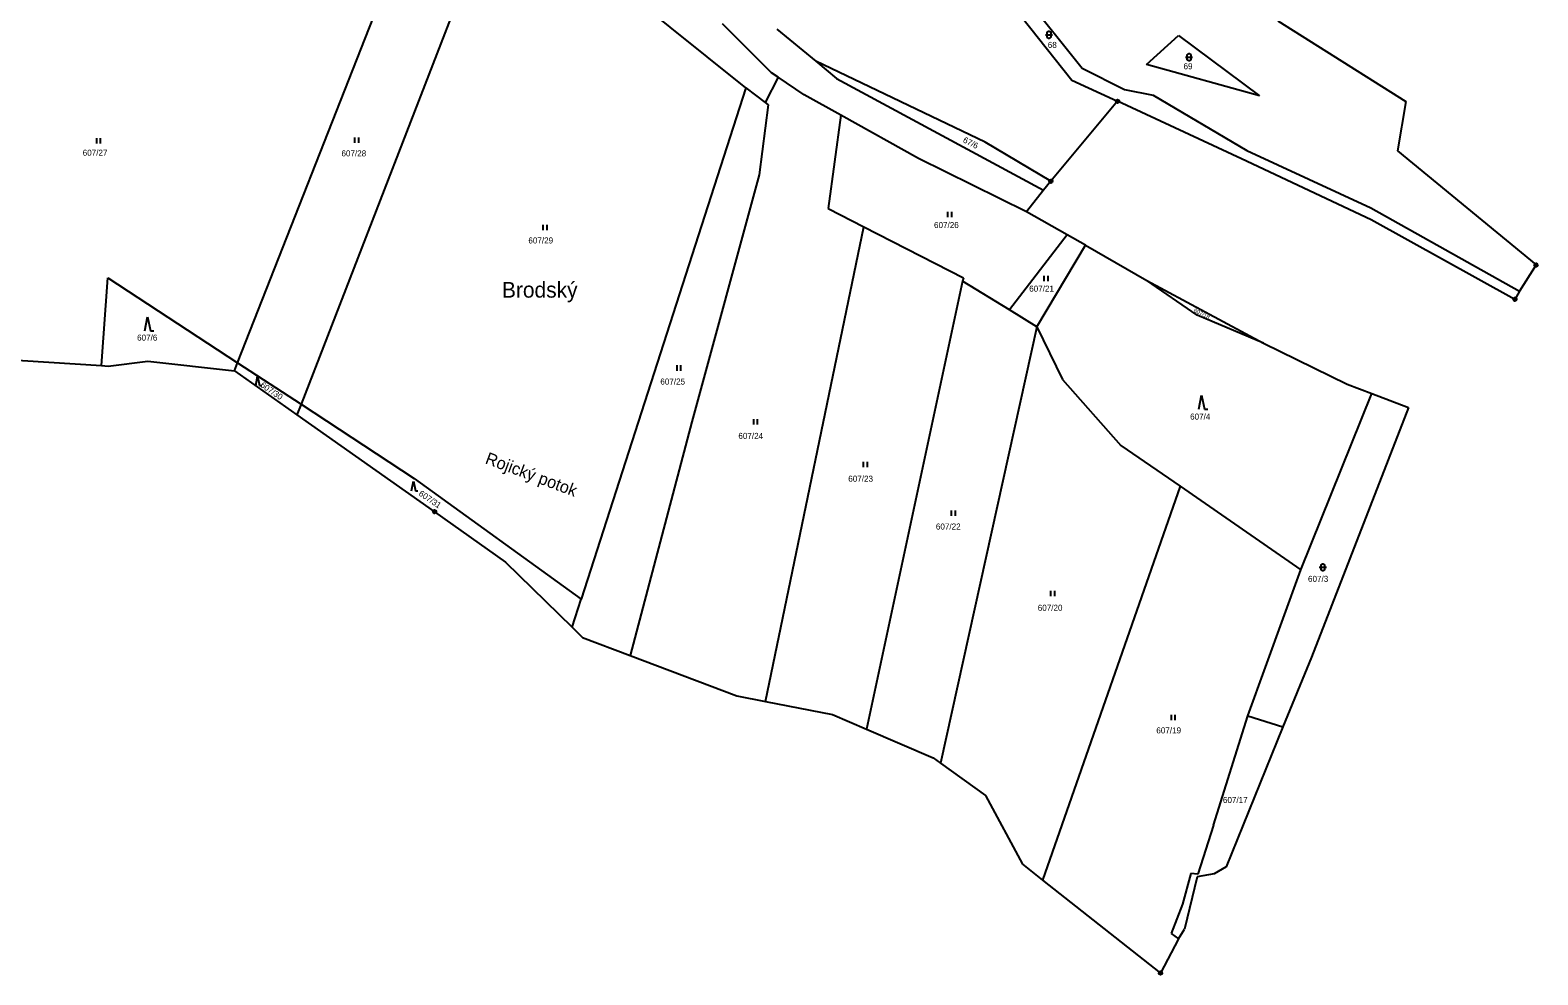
# Model space of a CAD drawing. Extents: x -794421 to -792735, y -1117671 to -1115559.
# Drawn here: x -793344.4 to -792920.6, y -1117671.2 to -1117405.7 of the extents above; entities that cross this region are included whole.
import ezdxf

# ---------------------------------------------------------------- set-up
doc = ezdxf.new("R2010")
doc.units = 0
for name, color, linetype in [('Vrstva 1', 7, 'Continuous'), ('Vrstva 14', 7, 'Continuous'), ('Vrstva 23', 7, 'Continuous'), ('Vrstva 28', 7, 'Continuous'), ('Vrstva 39', 7, 'Continuous'), ('Vrstva 4', 7, 'Continuous'), ('Vrstva 43', 7, 'Continuous')]:
    doc.layers.add(name, color=color, linetype=linetype)

msp = doc.modelspace()

# ---------------------------------------------------------------- linework, layer by layer
at = {"layer": 'Vrstva 1'}
for p, q in [((-793286.1, -1117499.19), (-793232.53, -1117362.94)), ((-793214.85, -1117373.01), (-793268.27, -1117510.87)), ((-793143.2, -1117421.9), (-793178.43, -1117393.62)), ((-793072.2, -1117393.73), (-793051.64, -1117419.77)), ((-793068.56, -1117391.53), (-793048.75, -1117416.41)), ((-793136.06, -1117417.71), (-793149.83, -1117403.92)), ((-793134.52, -1117405.39), (-793123.59, -1117414.41)), ((-793030.58, -1117415.37), (-793021.66, -1117407.23)), ((-793021.66, -1117407.23), (-792998.85, -1117424.15)), ((-793123.59, -1117414.41), (-793117.73, -1117419.25)), ((-793075.95, -1117437.2), (-793123.59, -1117414.41)), ((-792998.85, -1117424.15), (-793030.58, -1117415.37)), ((-793134.19, -1117418.96), (-793137.78, -1117426.04)), ((-793134.19, -1117418.96), (-793136.06, -1117417.71)), ((-793126.8, -1117423.9), (-793134.19, -1117418.96)), ((-793117.73, -1117419.25), (-793059.57, -1117450.65)), ((-793051.64, -1117419.77), (-793038.78, -1117425.69)), ((-793048.75, -1117416.41), (-793036.78, -1117422.39)), ((-793143.2, -1117421.9), (-793189.53, -1117565.63)), ((-793143.2, -1117421.9), (-793137.78, -1117426.04)), ((-793116.56, -1117429.62), (-793126.8, -1117423.9)), ((-793036.78, -1117422.39), (-793028.75, -1117423.98)), ((-793028.75, -1117423.98), (-793002.45, -1117439.49)), ((-793136.98, -1117426.66), (-793139.46, -1117446.37)), ((-793137.78, -1117426.04), (-793136.98, -1117426.66)), ((-793116.56, -1117429.62), (-793120.12, -1117455.82)), ((-793094.72, -1117441.81), (-793116.56, -1117429.62)), ((-793057.52, -1117448.19), (-793075.95, -1117437.2)), ((-793064.39, -1117456.77), (-793094.72, -1117441.81)), ((-793002.45, -1117439.49), (-792967.59, -1117455.63)), ((-793139.46, -1117446.37), (-793158.4, -1117515.77)), ((-793120.12, -1117455.82), (-793110.11, -1117460.97)), ((-792967.59, -1117455.63), (-792925.73, -1117479.04)), ((-793137.7, -1117594.41), (-793110.11, -1117460.97)), ((-793110.11, -1117460.97), (-793082.1, -1117475.33)), ((-793052.96, -1117463.24), (-793069.16, -1117484.35)), ((-793061.46, -1117489.1), (-793047.78, -1117466.17)), ((-793324.32, -1117499.98), (-793322.58, -1117475.28)), ((-793322.58, -1117475.28), (-793286.1, -1117499.19)), ((-793082.1, -1117475.33), (-793082.3, -1117476.24)), ((-793082.3, -1117476.24), (-793109.33, -1117602.18)), ((-793069.16, -1117484.35), (-793082.3, -1117476.24)), ((-793016.37, -1117485.78), (-793030.56, -1117476.1)), ((-793061.46, -1117489.1), (-793069.16, -1117484.35)), ((-792997.7, -1117493.71), (-793016.37, -1117485.78)), ((-793061.46, -1117489.1), (-793088.55, -1117611.72)), ((-793061.46, -1117489.1), (-793054.2, -1117503.86)), ((-793287, -1117501.49), (-793286.1, -1117499.19)), ((-793286.1, -1117499.19), (-793268.27, -1117510.87)), ((-793054.2, -1117503.86), (-793037.83, -1117522.49)), ((-792987.22, -1117557.42), (-792967.25, -1117507.86)), ((-793268.27, -1117510.87), (-793269.42, -1117513.84)), ((-793268.27, -1117510.87), (-793236.49, -1117531.69)), ((-793158.4, -1117515.77), (-793175.72, -1117581.5)), ((-793037.83, -1117522.49), (-793021.17, -1117533.91)), ((-793236.49, -1117531.69), (-793189.53, -1117565.63)), ((-793021.17, -1117533.91), (-793059.81, -1117644.62)), ((-793021.17, -1117533.91), (-792987.22, -1117557.42)), ((-793002.15, -1117598.46), (-792987.22, -1117557.42)), ((-793192.08, -1117573.55), (-793189.53, -1117565.63)), ((-793011.83, -1117629.19), (-793002.15, -1117598.46)), ((-793002.15, -1117598.46), (-792992.26, -1117601.54)), ((-793011.83, -1117629.19), (-793016.15, -1117642.96)), ((-793018.19, -1117642.77), (-793020.47, -1117651.32)), ((-793016.15, -1117642.96), (-793018.19, -1117642.77)), ((-793020.47, -1117651.32), (-793023.73, -1117659.61)), ((-793023.73, -1117659.61), (-793021.58, -1117661.13))]:
    msp.add_line(p, q, dxfattribs=at)
at = {"layer": 'Vrstva 23'}
for p, q in [((-793059.05, -1117407.01), (-793057.05, -1117407.01)), ((-793058.55, -1117406.41), (-793058.45, -1117406.21)), ((-793058.55, -1117407.61), (-793058.55, -1117406.41)), ((-793058.45, -1117407.81), (-793058.55, -1117407.61)), ((-793058.45, -1117406.21), (-793058.35, -1117406.11)), ((-793058.35, -1117407.91), (-793058.45, -1117407.81)), ((-793058.35, -1117406.11), (-793058.15, -1117406.01)), ((-793058.15, -1117408.01), (-793058.35, -1117407.91)), ((-793058.15, -1117406.01), (-793057.95, -1117406.01)), ((-793057.95, -1117406.01), (-793057.75, -1117406.11)), ((-793057.75, -1117407.91), (-793057.95, -1117408.01)), ((-793057.75, -1117406.11), (-793057.65, -1117406.21)), ((-793057.65, -1117407.81), (-793057.75, -1117407.91)), ((-793057.65, -1117406.21), (-793057.55, -1117406.41)), ((-793057.55, -1117407.61), (-793057.65, -1117407.81)), ((-793057.55, -1117406.41), (-793057.55, -1117407.61)), ((-793057.95, -1117408.01), (-793058.15, -1117408.01)), ((-793019.65, -1117413.3), (-793017.65, -1117413.3)), ((-793019.15, -1117412.7), (-793019.05, -1117412.5)), ((-793019.15, -1117413.9), (-793019.15, -1117412.7)), ((-793019.05, -1117414.1), (-793019.15, -1117413.9)), ((-793019.05, -1117412.5), (-793018.95, -1117412.4)), ((-793018.95, -1117414.2), (-793019.05, -1117414.1)), ((-793018.95, -1117412.4), (-793018.75, -1117412.3)), ((-793018.75, -1117414.3), (-793018.95, -1117414.2)), ((-793018.75, -1117412.3), (-793018.55, -1117412.3)), ((-793018.55, -1117414.3), (-793018.75, -1117414.3)), ((-793018.55, -1117412.3), (-793018.35, -1117412.4)), ((-793018.35, -1117414.2), (-793018.55, -1117414.3)), ((-793018.35, -1117412.4), (-793018.25, -1117412.5)), ((-793018.25, -1117414.1), (-793018.35, -1117414.2)), ((-793018.25, -1117412.5), (-793018.15, -1117412.7)), ((-793018.15, -1117413.9), (-793018.25, -1117414.1)), ((-793018.15, -1117412.7), (-793018.15, -1117413.9)), ((-793325.68, -1117437.57), (-793325.68, -1117436.07)), ((-793324.68, -1117436.07), (-793324.68, -1117437.57)), ((-793253.13, -1117437.34), (-793253.13, -1117435.84)), ((-793252.13, -1117435.84), (-793252.13, -1117437.34)), ((-793086.44, -1117458.25), (-793086.44, -1117456.75)), ((-793085.44, -1117456.75), (-793085.44, -1117458.25)), ((-793200.22, -1117461.91), (-793200.22, -1117460.41)), ((-793199.22, -1117460.41), (-793199.22, -1117461.91)), ((-793059.38, -1117476.28), (-793059.38, -1117474.78)), ((-793058.38, -1117474.78), (-793058.38, -1117476.28)), ((-793312.2, -1117490.24), (-793311.4, -1117486.24)), ((-793311.4, -1117486.24), (-793310.6, -1117490.24)), ((-793310.6, -1117490.24), (-793309.6, -1117490.24)), ((-793162.58, -1117501.41), (-793162.58, -1117499.91)), ((-793161.58, -1117499.91), (-793161.58, -1117501.41)), ((-793280.996, -1117505.6), (-793280.46, -1117502.92)), ((-793280.46, -1117502.92), (-793279.924, -1117505.6)), ((-793279.924, -1117505.6), (-793279.254, -1117505.6)), ((-793015.94, -1117512.26), (-793015.14, -1117508.26)), ((-793015.14, -1117508.26), (-793014.34, -1117512.26)), ((-793014.34, -1117512.26), (-793013.34, -1117512.26)), ((-793141.03, -1117516.56), (-793141.03, -1117515.06)), ((-793140.03, -1117515.06), (-793140.03, -1117516.56)), ((-793110.16, -1117528.51), (-793110.16, -1117527.01)), ((-793109.16, -1117527.01), (-793109.16, -1117528.51)), ((-793237.176, -1117535.19), (-793236.64, -1117532.51)), ((-793236.64, -1117532.51), (-793236.104, -1117535.19)), ((-793236.104, -1117535.19), (-793235.434, -1117535.19)), ((-793085.41, -1117542.2), (-793085.41, -1117540.7)), ((-793084.41, -1117540.7), (-793084.41, -1117542.2)), ((-792981.55, -1117556.07), (-792981.45, -1117555.87)), ((-792981.55, -1117557.27), (-792981.55, -1117556.07)), ((-792981.45, -1117555.87), (-792981.35, -1117555.77)), ((-792981.35, -1117555.77), (-792981.15, -1117555.67)), ((-792981.15, -1117555.67), (-792980.95, -1117555.67)), ((-792980.95, -1117555.67), (-792980.75, -1117555.77)), ((-792980.75, -1117555.77), (-792980.65, -1117555.87)), ((-792980.65, -1117555.87), (-792980.55, -1117556.07)), ((-792980.55, -1117556.07), (-792980.55, -1117557.27)), ((-792982.05, -1117556.67), (-792980.05, -1117556.67)), ((-792981.45, -1117557.47), (-792981.55, -1117557.27)), ((-792981.35, -1117557.57), (-792981.45, -1117557.47)), ((-792981.15, -1117557.67), (-792981.35, -1117557.57)), ((-792980.95, -1117557.67), (-792981.15, -1117557.67)), ((-792980.75, -1117557.57), (-792980.95, -1117557.67)), ((-792980.65, -1117557.47), (-792980.75, -1117557.57)), ((-792980.55, -1117557.27), (-792980.65, -1117557.47)), ((-793057.47, -1117564.77), (-793057.47, -1117563.27)), ((-793056.47, -1117563.27), (-793056.47, -1117564.77)), ((-793023.62, -1117599.67), (-793023.62, -1117598.17)), ((-793022.62, -1117598.17), (-793022.62, -1117599.67))]:
    msp.add_line(p, q, dxfattribs=at)
at = {"layer": 'Vrstva 28'}
for centre, radius in [((-793038.78, -1117425.69), 0.5), ((-793038.78, -1117425.69), 0.01), ((-793057.52, -1117448.19), 0.5), ((-793057.52, -1117448.19), 0.01), ((-792921.12, -1117471.7), 0.5), ((-792921.12, -1117471.7), 0.01), ((-792927.05, -1117481.37), 0.5), ((-792927.05, -1117481.37), 0.01), ((-793230.71, -1117541.05), 0.5), ((-793230.71, -1117541.05), 0.01), ((-793026.68, -1117670.73), 0.5), ((-793026.68, -1117670.73), 0.01)]:
    msp.add_circle(centre, radius, dxfattribs=at)
at = {"layer": 'Vrstva 4'}
for p, q in [((-792993.66, -1117403.11), (-792957.73, -1117425.76)), ((-793038.78, -1117425.69), (-793057.52, -1117448.19)), ((-793003.93, -1117441.86), (-793038.78, -1117425.69)), ((-792957.73, -1117425.76), (-792960.06, -1117439.6)), ((-792960.06, -1117439.6), (-792921.12, -1117471.7)), ((-792967.43, -1117458.98), (-793003.93, -1117441.86)), ((-793057.52, -1117448.19), (-793059.57, -1117450.65)), ((-793059.57, -1117450.65), (-793064.39, -1117456.77)), ((-793052.96, -1117463.24), (-793064.39, -1117456.77)), ((-792927.05, -1117481.37), (-792967.43, -1117458.98)), ((-793047.78, -1117466.17), (-793052.96, -1117463.24)), ((-793047.78, -1117466.17), (-793030.56, -1117476.1)), ((-792921.12, -1117471.7), (-792925.73, -1117479.04)), ((-793030.56, -1117476.1), (-792997.7, -1117493.71)), ((-792925.73, -1117479.04), (-792927.05, -1117481.37)), ((-792997.7, -1117493.71), (-792974.2, -1117505.22)), ((-793366.2, -1117497.33), (-793324.32, -1117499.98)), ((-793324.32, -1117499.98), (-793322.48, -1117500.1)), ((-793322.48, -1117500.1), (-793311.33, -1117498.72)), ((-793311.33, -1117498.72), (-793287, -1117501.49)), ((-793287, -1117501.49), (-793269.42, -1117513.84)), ((-792974.2, -1117505.22), (-792967.25, -1117507.86)), ((-792967.25, -1117507.86), (-792957.01, -1117511.74)), ((-793269.42, -1117513.84), (-793230.71, -1117541.05)), ((-792957.01, -1117511.74), (-792984.27, -1117581.91)), ((-793230.71, -1117541.05), (-793210.83, -1117555.22)), ((-793210.83, -1117555.22), (-793192.08, -1117573.55)), ((-793192.08, -1117573.55), (-793189.15, -1117576.42)), ((-793189.15, -1117576.42), (-793175.72, -1117581.5)), ((-793175.72, -1117581.5), (-793145.76, -1117592.85)), ((-792984.27, -1117581.91), (-792992.26, -1117601.54)), ((-793145.76, -1117592.85), (-793137.7, -1117594.41)), ((-793137.7, -1117594.41), (-793118.91, -1117598.04)), ((-793118.91, -1117598.04), (-793109.33, -1117602.18)), ((-793109.33, -1117602.18), (-793090.59, -1117610.26)), ((-792992.26, -1117601.54), (-793008.27, -1117640.87)), ((-793090.59, -1117610.26), (-793088.55, -1117611.72)), ((-793088.55, -1117611.72), (-793075.88, -1117620.82)), ((-793075.88, -1117620.82), (-793065.51, -1117640.13)), ((-793065.51, -1117640.13), (-793059.81, -1117644.62)), ((-793008.27, -1117640.87), (-793011.61, -1117642.83)), ((-793059.81, -1117644.62), (-793026.68, -1117670.73)), ((-793016.37, -1117643.66), (-793019.95, -1117658.38)), ((-793011.61, -1117642.83), (-793016.37, -1117643.66)), ((-793021.58, -1117661.13), (-793026.68, -1117670.73)), ((-793021.58, -1117661.13), (-793019.95, -1117658.38))]:
    msp.add_line(p, q, dxfattribs=at)

# ---------------------------------------------------------------- texts
at = {"layer": 'Vrstva 14'}
for s, p in [('68', (-793058.367, -1117410.7)), ('69', (-793020.207, -1117416.69)), ('607/27', (-793329.632, -1117441)), ('607/28', (-793256.905, -1117441.18)), ('607/26', (-793090.345, -1117461.33)), ('607/29', (-793204.365, -1117465.66)), ('607/21', (-793063.589, -1117479.2)), ('607/6', (-793314.346, -1117492.97)), ('607/25', (-793167.272, -1117505.32)), ('607/4', (-793018.362, -1117515.17)), ('607/24', (-793145.341, -1117520.59)), ('607/23', (-793114.445, -1117532.63)), ('607/22', (-793089.815, -1117546.07)), ('607/3', (-792985.226, -1117560.78)), ('607/20', (-793061.185, -1117568.9)), ('607/19', (-793027.859, -1117603.37)), ('607/17', (-793009.135, -1117622.93))]:
    msp.add_text(s, height=1.7, dxfattribs=at).set_placement(p)
for s, height, rotation, p in [('67/6', 1.7, 332.81649, (-793082.387, -1117437.127)), ('607/18', 1.14, 332.87328, (-793017.486, -1117484.811)), ('607/30', 1.7, 325.9953, (-793279.889, -1117505.852)), ('607/31', 1.7, 325.90395, (-793235.359, -1117536.318))]:
    msp.add_text(s, height=height, rotation=rotation, dxfattribs=at).set_placement(p)
at = {"layer": 'Vrstva 39'}
msp.add_text('Brodský', height=4.4, dxfattribs=at).set_placement((-793211.79, -1117480.88))
at = {"layer": 'Vrstva 43'}
msp.add_text('Rojický potok', height=3.4, rotation=339.48369, dxfattribs=at).set_placement((-793216.75, -1117527.41))

doc.saveas('drawing.dxf')
